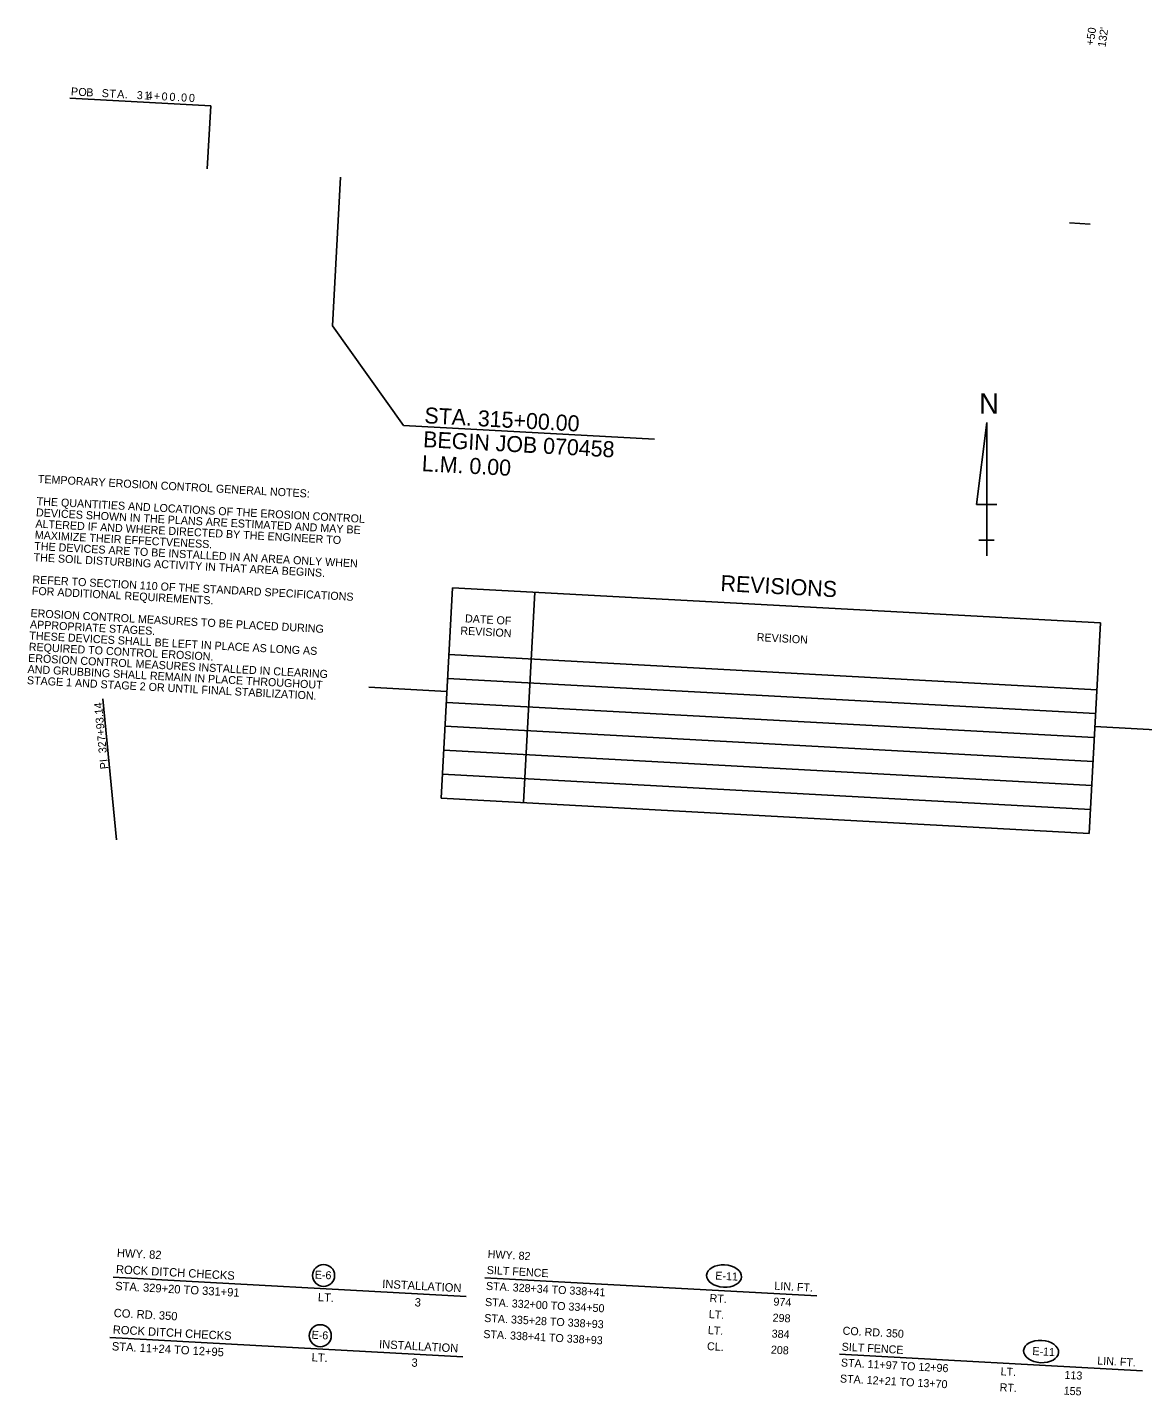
# Model space of a CAD drawing. Extents: x 881123 to 882718, y 1566283 to 1567356.
# Drawn here: x 881123 to 881960, y 1566330 to 1567356 of the extents above; entities that cross this region are included whole.
import ezdxf

# ---------------------------------------------------------------- set-up
doc = ezdxf.new("R2010")
doc.units = 0
for name, color, linetype in [('Default', 7, 'Continuous'), ('R_Border', 7, 'Continuous'), ('R_Border Prem', 7, 'Continuous'), ('R_Draft', 7, 'Continuous'), ('R_Logo', 7, 'Continuous'), ('STAMP', 7, 'Continuous'), ('STAMP_PP', 7, 'Continuous')]:
    doc.layers.add(name, color=color, linetype=linetype)

msp = doc.modelspace()

# ---------------------------------------------------------------- linework, layer by layer
at = {"layer": 'Default'}
for p, q in [((881187.8, 1566419.1), (881452.5, 1566404.7)), ((881185.4, 1566373.9), (881450, 1566359.5))]:
    msp.add_line(p, q, dxfattribs=at)
at = {"layer": 'R_Border'}
for p, q in [((881358.2, 1567243.8), (881352.2, 1567132.4)), ((881352.2, 1567132.4), (881405.5, 1567057.6)), ((881405.5, 1567057.6), (881593.9, 1567047.4)), ((881466.6, 1566418.7), (881715.5, 1566405.2)), ((881732.7, 1566361.3), (881959.8, 1566349))]:
    msp.add_line(p, q, dxfattribs=at)
at = {"layer": 'R_Border Prem'}
for p, q in [((881843, 1567060), (881835.3, 1566998.5)), ((881843, 1566960), (881843, 1567060)), ((881843, 1567060), (881843, 1566983.1)), ((881835.3, 1566998.5), (881850.7, 1566998.5)), ((881843, 1566960), (881843, 1566983.1)), ((881843, 1566971.6), (881837.2, 1566971.6)), ((881837.2, 1566971.6), (881848.7, 1566971.6)), ((881843, 1566960), (881843, 1566971.6)), ((881438.1, 1566858.3), (881379.5, 1566861.5)), ((882371, 1566807.6), (881924.2, 1566831.9))]:
    msp.add_line(p, q, dxfattribs=at)
at = {"layer": 'R_Draft'}
for centre in [(881345.6, 1566420.4), (881343.1, 1566375.2)]:
    msp.add_circle(centre, 8.26, dxfattribs=at)
for centre in [(881646, 1566420), (881883.8, 1566363.4)]:
    msp.add_ellipse(centre, major_axis=(13.1, -0.7), ratio=0.638788, dxfattribs=at)
at = {"layer": 'R_Logo'}
for p, q in [((881442.3, 1566936), (881433.7, 1566778.2)), ((881442.3, 1566936), (881928.4, 1566909.6)), ((881504, 1566932.7), (881495.5, 1566774.9)), ((881928.4, 1566909.6), (881919.8, 1566751.8)), ((881439.6, 1566886.1), (881925.7, 1566859.6)), ((881438.6, 1566868.1), (881924.7, 1566841.7)), ((881437.7, 1566850.1), (881923.7, 1566823.7)), ((881436.7, 1566832.2), (881922.8, 1566805.7)), ((881435.7, 1566814.2), (881921.8, 1566787.8)), ((881434.7, 1566796.2), (881920.8, 1566769.8)), ((881433.7, 1566778.2), (881919.8, 1566751.8))]:
    msp.add_line(p, q, dxfattribs=at)
at = {"layer": 'STAMP_PP'}
for p, q in [((881261, 1567297.3), (881155.2, 1567303.1)), ((881258.4, 1567250), (881261, 1567297.3)), ((881905.2, 1567209.7), (881920.5, 1567208.7))]:
    msp.add_line(p, q, dxfattribs=at)
msp.add_lwpolyline([(881190.4, 1566747), (881180.1, 1566852.8)], dxfattribs=at)

# ---------------------------------------------------------------- texts
at = {"layer": 'Default'}
for s, p in [('HWY. 82', (881190.5, 1566434.4)), ('ROCK DITCH CHECKS', (881189.8, 1566422)), ('STA. 329+20 TO 331+91', (881189.2, 1566409.5)), ('INSTALLATION', (881389.5, 1566411.1)), (' LT.', (881338.9, 1566401.3)), ('3', (881413.8, 1566397.3)), ('CO. RD. 350', (881188.1, 1566389.3)), ('ROCK DITCH CHECKS', (881187.4, 1566376.8)), ('STA. 11+24 TO 12+95', (881186.7, 1566364.3)), ('INSTALLATION', (881387.1, 1566365.9)), ('LT.', (881336.5, 1566356.1)), ('3', (881411.4, 1566352.1))]:
    msp.add_text(s, height=6.25, rotation=356.8871, dxfattribs=at).set_placement(p)
at = {"layer": 'R_Border'}
for s, height, p in [('STA. 315+00.00', 12, (881421, 1567059.4)), ('BEGIN JOB 070458', 12, (881420.1, 1567041.5)), ('L.M. 0.00', 12, (881419.1, 1567023.5)), ('TEMPORARY EROSION CONTROL GENERAL NOTES:', 6, (881131.2, 1567014.7)), ('DEVICES SHOWN IN THE PLANS ARE ESTIMATED AND MAY BE', 6, (881129.8, 1566989.6)), ('THE QUANTITIES AND LOCATIONS OF THE EROSION CONTROL', 6, (881130.3, 1566998)), ('ALTERED IF AND WHERE DIRECTED BY THE ENGINEER TO', 6, (881129.4, 1566981.2)), ('MAXIMIZE THEIR EFFECTVENESS.', 6, (881128.9, 1566972.8)), ('THE DEVICES ARE TO BE INSTALLED IN AN AREA ONLY WHEN', 6, (881128.5, 1566964.4)), ('THE SOIL DISTURBING ACTIVITY IN THAT AREA BEGINS.', 6, (881128, 1566956)), ('REFER TO SECTION 110 OF THE STANDARD SPECIFICATIONS', 6, (881127.1, 1566939.3)), ('FOR ADDITIONAL REQUIREMENTS.', 6, (881126.7, 1566930.9)), ('EROSION CONTROL MEASURES TO BE PLACED DURING', 6, (881125.7, 1566914.1)), ('APPROPRIATE STAGES. ', 6, (881125.3, 1566905.7)), ('THESE DEVICES SHALL BE LEFT IN PLACE AS LONG AS', 6, (881124.8, 1566897.3)), ('REQUIRED TO CONTROL EROSION.', 6, (881124.4, 1566888.9)), ('EROSION CONTROL MEASURES INSTALLED IN CLEARING', 6, (881123.9, 1566880.5)), ('AND GRUBBING SHALL REMAIN IN PLACE THROUGHOUT', 6, (881123.5, 1566872.2)), ('STAGE 1 AND STAGE 2 OR UNTIL FINAL STABILIZATION.', 6, (881123, 1566863.8)), ('HWY. 82', 6, (881468.6, 1566433.6)), ('SILT FENCE', 6, (881467.9, 1566421.6)), ('STA. 328+34 TO 338+41', 6, (881467.3, 1566409.6)), ('LIN. FT.', 6, (881683.6, 1566409.8)), ('STA. 332+00 TO 334+50', 6, (881466.6, 1566397.6)), ('RT. ', 6, (881635, 1566400.5)), ('974', 6, (881682.9, 1566397.9)), ('STA. 335+28 TO 338+93', 6, (881466, 1566385.6)), ('LT.', 6, (881634.4, 1566388.5)), ('298', 6, (881682.3, 1566385.9)), ('LT.', 6, (881633.7, 1566376.5)), ('384', 6, (881681.6, 1566373.9)), ('CO. RD. 350', 6, (881734.8, 1566376.1)), ('STA. 338+41 TO 338+93', 6, (881465.3, 1566373.6)), ('CL.', 6, (881633.1, 1566364.5)), ('SILT FENCE', 6, (881734.1, 1566364.1)), ('208', 6, (881681, 1566361.9)), ('LIN. FT.', 6, (881925.8, 1566353.7)), ('STA. 11+97 TO 12+96', 6, (881733.5, 1566352.2)), ('LT. ', 6, (881853.3, 1566345.6)), ('STA. 12+21 TO 13+70', 6, (881732.8, 1566340.2)), ('RT.', 6, (881852.6, 1566333.7)), ('113', 6, (881901.2, 1566343)), ('155', 6, (881900.6, 1566331.1))]:
    msp.add_text(s, height=height, rotation=356.8871, dxfattribs=at).set_placement(p)
at = {"layer": 'R_Border Prem'}
msp.add_text('N', height=15.4, rotation=360, dxfattribs=at).set_placement((881837.3, 1567066.5))
at = {"layer": 'R_Draft'}
for s, rotation, p in [('E-6 ', 357.2876, (881338.9, 1566418.1)), ('E-11', 357.1015, (881639.3, 1566417.4)), ('E-6 ', 357.2876, (881336.5, 1566373)), ('E-11', 357.1015, (881877.1, 1566360.8))]:
    msp.add_text(s, height=6, rotation=rotation, dxfattribs=at).set_placement(p)
at = {"layer": 'R_Logo'}
for s, height, p in [('REVISIONS', 12, (881643.1, 1566933.6)), ('DATE OF', 6, (881451.6, 1566910.1)), ('REVISION', 6, (881448.1, 1566901)), ('REVISION', 6, (881670.4, 1566896.1))]:
    msp.add_text(s, height=height, rotation=356.8871, dxfattribs=at).set_placement(p)
at = {"layer": 'STAMP'}
for s, p in [('+50', (881923.2, 1567342.2)), ("132'", (881932.1, 1567341))]:
    msp.add_text(s, height=6, rotation=81.8219, dxfattribs=at).set_placement(p)
at = {"layer": 'STAMP_PP'}
for s, rotation, p in [('P', 356.8871, (881156, 1567305.2)), ('O', 356.8871, (881161.6, 1567304.9)), ('B', 356.8871, (881167.5, 1567304.6)), ('S', 356.8871, (881179.1, 1567304)), ('T', 356.8871, (881184.8, 1567303.6)), ('A', 356.8871, (881190.7, 1567303.3)), ('.', 356.8871, (881196.5, 1567303)), ('3', 356.8871, (881205.4, 1567302.5)), ('1', 356.8871, (881210.8, 1567302.2)), ('4', 356.8871, (881212.8, 1567302.1)), ('+', 356.8871, (881218.2, 1567301.8)), ('0', 356.8871, (881224, 1567301.5)), ('0', 356.8871, (881229.9, 1567301.2)), ('0', 356.8871, (881238.6, 1567300.7)), ('0', 356.8871, (881244.5, 1567300.4)), ('.', 356.8871, (881235.7, 1567300.9)), ('PI  327+93.14', 95.5467, (881184.2, 1566800.3))]:
    msp.add_text(s, height=6, rotation=rotation, dxfattribs=at).set_placement(p)

doc.saveas('drawing.dxf')
